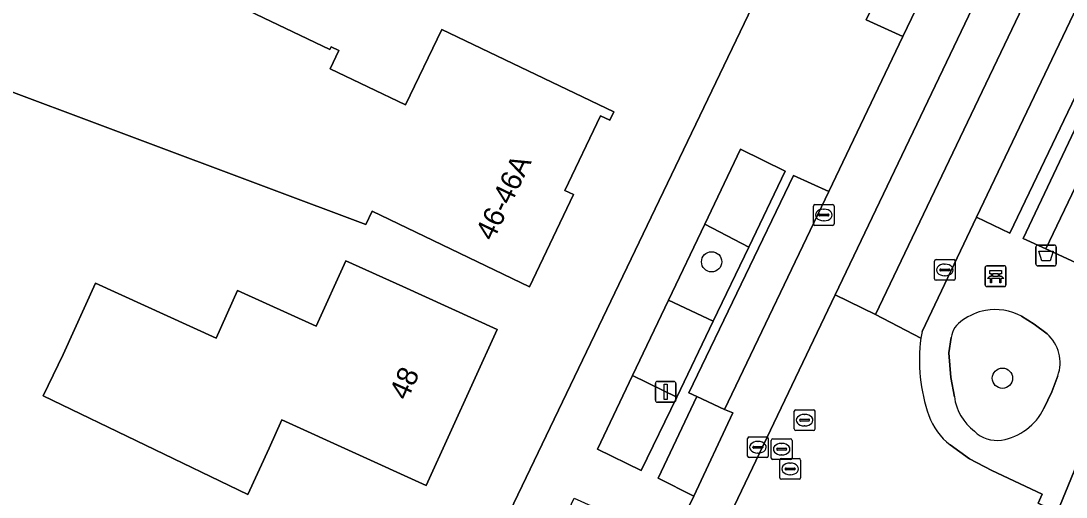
# Model space of a CAD drawing. Extents: x 161354 to 162026, y 386504 to 387460.
# Drawn here: x 161625.4 to 161675.8, y 386969.8 to 386992.8 of the extents above; entities that cross this region are included whole.
import ezdxf

# ---------------------------------------------------------------- set-up
doc = ezdxf.new("R2010")
doc.units = 0
for name, color, linetype in [('IMGEO_Afvalbak', 7, 'Continuous'), ('IMGEO_Bank', 7, 'Continuous'), ('IMGEO_Boom', 7, 'Continuous'), ('IMGEO_Erf', 7, 'Continuous'), ('IMGEO_Groenvoorziening', 7, 'Continuous'), ('IMGEO_Kolk', 7, 'Continuous'), ('IMGEO_Lichtmast', 7, 'Continuous'), ('IMGEO_Pand', 7, 'Continuous'), ('IMGEO_Pand_nummerreeks', 7, 'Continuous'), ('IMGEO_Parkeervlak_open', 7, 'Continuous'), ('IMGEO_Rijbaan_lokaal_open', 7, 'Continuous'), ('IMGEO_Rioolput', 7, 'Continuous'), ('IMGEO_Voetpad_open', 7, 'Continuous')]:
    doc.layers.add(name, color=color, linetype=linetype)

msp = doc.modelspace()

# ---------------------------------------------------------------- linework, layer by layer
at = {"layer": 'IMGEO_Afvalbak'}
for p, q in [((161674.479, 386981.982), (161675.269, 386981.982)), ((161675.269, 386981.982), (161674.479, 386981.982)), ((161674.379, 386981.082), (161674.379, 386981.882)), ((161674.379, 386981.882), (161674.379, 386981.082)), ((161675.369, 386981.882), (161675.369, 386981.082)), ((161675.369, 386981.082), (161675.369, 386981.882)), ((161675.269, 386980.982), (161674.479, 386980.982)), ((161674.479, 386980.982), (161675.269, 386980.982))]:
    msp.add_line(p, q, dxfattribs=at)
msp.add_lwpolyline([(161674.522, 386981.696), (161675.226, 386981.696), (161675.077, 386981.226), (161674.671, 386981.226), (161674.522, 386981.696)], dxfattribs=at)
for centre, start, end in [((161674.479, 386981.882), 90, 180), ((161674.479, 386981.882), 90, 180), ((161675.269, 386981.882), 0, 90), ((161675.269, 386981.882), 360, 90), ((161674.479, 386981.082), 180, 270), ((161674.479, 386981.082), 180, 270), ((161675.269, 386981.082), 270, 0), ((161675.269, 386981.082), 270, 0)]:
    msp.add_arc(centre, 0.1, start, end, dxfattribs=at)
at = {"layer": 'IMGEO_Bank'}
for p, q in [((161672.014, 386980.981), (161672.855, 386980.981)), ((161672.855, 386980.981), (161672.014, 386980.981)), ((161671.939, 386980.056), (161671.939, 386980.897)), ((161671.939, 386980.897), (161671.939, 386980.056)), ((161672.248, 386980.487), (161672.248, 386980.593)), ((161672.292, 386980.593), (161672.292, 386980.487)), ((161672.58, 386980.599), (161672.298, 386980.599)), ((161672.298, 386980.481), (161672.58, 386980.481)), ((161672.586, 386980.487), (161672.586, 386980.593)), ((161672.63, 386980.593), (161672.63, 386980.487)), ((161672.939, 386980.906), (161672.939, 386980.065)), ((161672.939, 386980.065), (161672.939, 386980.906)), ((161672.864, 386979.981), (161672.023, 386979.981)), ((161672.023, 386979.981), (161672.864, 386979.981)), ((161672.636, 386980.379), (161672.243, 386980.379))]:
    msp.add_line(p, q, dxfattribs=at)
for points in [[(161672.186, 386980.379), (161672.044, 386980.379), (161672.156, 386980.481), (161672.242, 386980.481)], [(161672.242, 386980.599), (161672.156, 386980.599), (161672.156, 386980.76), (161672.719, 386980.76), (161672.719, 386980.599), (161672.636, 386980.599)], [(161672.636, 386980.481), (161672.719, 386980.481), (161672.831, 386980.379), (161672.692, 386980.379)], [(161672.236, 386980.372), (161672.236, 386980.165), (161672.193, 386980.165), (161672.193, 386980.372)], [(161672.686, 386980.372), (161672.686, 386980.165), (161672.642, 386980.165), (161672.642, 386980.372)]]:
    msp.add_lwpolyline(points, dxfattribs=at)
for centre, radius, start, end in [((161672.017, 386980.903), 0.0779, 92.4484, 184.2845), ((161672.017, 386980.903), 0.0779, 92.4484, 184.2845), ((161672.861, 386980.903), 0.0779, 2.4484, 94.2845), ((161672.861, 386980.903), 0.0779, 2.4484, 94.2845), ((161672.241, 386980.592), 0.00671, 2.8957, 87.1043), ((161672.241, 386980.488), 0.00671, 272.8957, 357.1043), ((161672.298, 386980.592), 0.00671, 92.8957, 177.1043), ((161672.298, 386980.488), 0.00671, 182.8957, 267.1043), ((161672.58, 386980.592), 0.00671, 2.8957, 87.1043), ((161672.58, 386980.488), 0.00671, 272.8957, 357.1043), ((161672.637, 386980.592), 0.00671, 92.8957, 177.1043), ((161672.637, 386980.488), 0.00671, 182.8957, 267.1043), ((161672.017, 386980.059), 0.0779, 182.4484, 274.2845), ((161672.017, 386980.059), 0.0779, 182.4484, 274.2845), ((161672.186, 386980.372), 0.00671, 2.8957, 87.1043), ((161672.243, 386980.372), 0.00671, 92.8957, 177.1043), ((161672.635, 386980.372), 0.00671, 2.8957, 87.1043), ((161672.692, 386980.372), 0.00671, 92.8957, 177.1043), ((161672.861, 386980.059), 0.0779, 272.4484, 4.2845), ((161672.861, 386980.059), 0.0779, 272.4484, 4.2845)]:
    msp.add_arc(centre, radius, start, end, dxfattribs=at)
at = {"layer": 'IMGEO_Boom'}
for centre in [(161658.732, 386981.177), (161672.771, 386975.56)]:
    msp.add_circle(centre, 0.489, dxfattribs=at)
at = {"layer": 'IMGEO_Erf'}
for points in [[(161639.028, 387030.532), (161638.508, 387014.846), (161634.791, 387006.94), (161635.073, 387006.762), (161631.945, 387000), (161630.209, 386996.251), (161636.023, 386993.468), (161640.299, 386991.421), (161640.365, 386991.559), (161640.742, 386991.379), (161640.319, 386990.494), (161643.964, 386988.749), (161645.705, 386992.384), (161649.5, 386990.567), (161654.01, 386988.408), (161653.819, 386988.01), (161653.371, 386988.225), (161651.645, 386984.62), (161652.067, 386984.418), (161649.94, 386979.976), (161642.34, 386983.614)], [(161627.852, 386924.437), (161646.394, 386963.7), (161647.042, 386965.072), (161663.81, 387000), (161675.489, 387024.329)], [(161642.34, 386983.614), (161642.038, 386982.983), (161637.356, 386984.735), (161616.468, 386992.553)]]:
    msp.add_lwpolyline(points, dxfattribs=at)
msp.add_lwpolyline([(161641.076, 386981.232), (161643.83, 386979.98), (161648.381, 386977.91), (161644.961, 386970.388), (161637.992, 386973.556), (161637.37, 386972.188), (161636.348, 386969.941), (161626.462, 386974.71), (161627.426, 386976.709), (161628.998, 386980.143), (161634.812, 386977.499), (161635.853, 386979.789), (161639.638, 386978.068)], close=True, dxfattribs=at)
at = {"layer": 'IMGEO_Groenvoorziening'}
for points in [[(161678.258, 386988.893), (161677.127, 386989.4), (161673.763, 386982.308), (161674.862, 386981.801)], [(161680.347, 386987.958), (161678.258, 386988.893), (161674.862, 386981.801), (161677.136, 386980.752)], [(161662.286, 386985.549), (161660.12, 386986.613), (161658.399, 386983), (161660.524, 386981.884)], [(161660.524, 386981.884), (161658.399, 386983), (161656.647, 386979.321), (161658.807, 386978.313)], [(161658.807, 386978.313), (161656.647, 386979.321), (161654.917, 386975.688), (161657.046, 386974.651)], [(161657.046, 386974.651), (161654.917, 386975.688), (161653.224, 386972.132), (161655.338, 386971.098)], [(161659.764, 386973.893), (161659.348, 386974.057), (161658.012, 386974.684), (161656.15, 386970.736), (161657.878, 386969.873)]]:
    msp.add_lwpolyline(points, close=True, dxfattribs=at)
for points in [[(161674.923, 386977.7), (161674.308, 386978.168), (161673.689, 386978.556)], [(161670.293, 386977.521), (161670.182, 386976.789), (161670.271, 386975.601), (161670.449, 386974.669)], [(161674.768, 386974.097), (161675.156, 386974.901), (161675.437, 386975.672)]]:
    msp.add_lwpolyline(points, dxfattribs=at)
for centre, radius, start, end in [((161672.464, 386976.096), 2.781, 100.7237, 125.4842), ((161672.433, 386976.235), 2.639, 61.5738, 100.6227), ((161671.487, 386977.335), 1.208, 121.86, 171.1385), ((161673.73, 386976.319), 1.825, 339.2507, 49.1937), ((161672.938, 386974.996), 2.51, 187.4792, 232.6228), ((161672.257, 386975.336), 2.8, 279.7591, 333.7281), ((161672.492, 386974.092), 1.534, 225.3394, 278.9946)]:
    msp.add_arc(centre, radius, start, end, dxfattribs=at)
at = {"layer": 'IMGEO_Kolk'}
for p, q in [((161663.647, 386983.011), (161663.647, 386983.863)), ((161663.722, 386983.937), (161664.574, 386983.937)), ((161664.135, 386983.717), (161664.16, 386983.717)), ((161664.648, 386983.863), (161664.648, 386983.011)), ((161663.906, 386983.431), (161663.906, 386983.443)), ((161664.344, 386983.394), (161663.946, 386983.394)), ((161663.949, 386983.48), (161664.347, 386983.48)), ((161664.158, 386983.157), (161664.133, 386983.157)), ((161664.39, 386983.443), (161664.39, 386983.431)), ((161664.574, 386982.937), (161663.722, 386982.937)), ((161669.49, 386980.359), (161669.49, 386981.211)), ((161669.565, 386981.285), (161670.417, 386981.285)), ((161669.978, 386981.065), (161670.003, 386981.065)), ((161670.491, 386981.211), (161670.491, 386980.359)), ((161669.749, 386980.779), (161669.749, 386980.791)), ((161670.187, 386980.742), (161669.789, 386980.742)), ((161669.792, 386980.828), (161670.19, 386980.828)), ((161670.001, 386980.505), (161669.976, 386980.505)), ((161670.233, 386980.791), (161670.233, 386980.779)), ((161670.417, 386980.285), (161669.565, 386980.285))]:
    msp.add_line(p, q, dxfattribs=at)
for points in [[(161663.647, 386983.011), (161663.647, 386983.863)], [(161663.722, 386983.937), (161664.574, 386983.937)], [(161664.648, 386983.863), (161664.648, 386983.011)], [(161664.574, 386982.937), (161663.722, 386982.937)], [(161669.49, 386980.359), (161669.49, 386981.211)], [(161669.565, 386981.285), (161670.417, 386981.285)], [(161670.491, 386981.211), (161670.491, 386980.359)], [(161670.417, 386980.285), (161669.565, 386980.285)]]:
    msp.add_lwpolyline(points, dxfattribs=at)
for centre, radius, start, end in [((161663.724, 386983.861), 0.0765, 91.552, 178.448), ((161663.724, 386983.861), 0.0765, 91.552, 178.448), ((161664.572, 386983.861), 0.0765, 1.552, 88.448), ((161664.572, 386983.861), 0.0765, 1.552, 88.448), ((161663.724, 386983.013), 0.0765, 181.552, 268.448), ((161663.724, 386983.013), 0.0765, 181.552, 268.448), ((161663.946, 386983.44), 0.0403, 85.8775, 175.7526), ((161663.943, 386983.43), 0.0366, 178.938, 274.7102), ((161664.347, 386983.437), 0.043, 264.8664, 352.4533), ((161664.351, 386983.442), 0.0386, 1.7309, 96.639), ((161664.572, 386983.013), 0.0765, 271.552, 358.448), ((161664.572, 386983.013), 0.0765, 271.552, 358.448), ((161669.567, 386981.209), 0.0765, 91.552, 178.448), ((161669.567, 386981.209), 0.0765, 91.552, 178.448), ((161670.415, 386981.209), 0.0765, 1.552, 88.448), ((161670.415, 386981.209), 0.0765, 1.552, 88.448), ((161669.789, 386980.788), 0.0403, 85.8775, 175.7526), ((161669.786, 386980.778), 0.0366, 178.938, 274.7102), ((161670.19, 386980.785), 0.043, 264.8664, 352.4533), ((161670.194, 386980.79), 0.0386, 1.7309, 96.639), ((161669.567, 386980.361), 0.0765, 181.552, 268.448), ((161669.567, 386980.361), 0.0765, 181.552, 268.448), ((161670.415, 386980.361), 0.0765, 271.552, 358.448), ((161670.415, 386980.361), 0.0765, 271.552, 358.448)]:
    msp.add_arc(centre, radius, start, end, dxfattribs=at)
for centre, major_axis, ratio, start_param, end_param in [((161664.134, 386983.437), (-0.387, 0.002), 0.722429, 4.712389, 7.853982), ((161664.159, 386983.437), (-0.39, 0.002), 0.717154, 1.570796, 4.712389), ((161669.977, 386980.785), (-0.387, 0.002), 0.722429, 4.712389, 7.853982), ((161670.002, 386980.785), (-0.39, 0.002), 0.717154, 1.570796, 4.712389)]:
    msp.add_ellipse(centre, major_axis=major_axis, ratio=ratio, start_param=start_param, end_param=end_param, dxfattribs=at)
at = {"layer": 'IMGEO_Lichtmast'}
for p, q in [((161656.018, 386974.501), (161656.018, 386975.301)), ((161656.018, 386975.301), (161656.018, 386974.501)), ((161656.118, 386975.401), (161656.908, 386975.401)), ((161656.908, 386975.401), (161656.118, 386975.401)), ((161657.008, 386975.301), (161657.008, 386974.501)), ((161657.008, 386974.501), (161657.008, 386975.301)), ((161656.908, 386974.401), (161656.118, 386974.401)), ((161656.118, 386974.401), (161656.908, 386974.401))]:
    msp.add_line(p, q, dxfattribs=at)
msp.add_lwpolyline([(161656.438, 386975.276), (161656.588, 386975.276), (161656.588, 386974.526), (161656.438, 386974.526), (161656.438, 386975.276)], dxfattribs=at)
for centre, start, end in [((161656.118, 386975.301), 90, 180), ((161656.118, 386975.301), 90, 180), ((161656.908, 386975.301), 0, 90), ((161656.908, 386975.301), 360, 90), ((161656.118, 386974.501), 180, 270), ((161656.118, 386974.501), 180, 270), ((161656.908, 386974.501), 270, 0), ((161656.908, 386974.501), 270, 0)]:
    msp.add_arc(centre, 0.1, start, end, dxfattribs=at)
at = {"layer": 'IMGEO_Pand'}
msp.add_lwpolyline([(161616.468, 386992.553), (161637.356, 386984.735), (161642.038, 386982.983), (161642.34, 386983.614), (161649.94, 386979.976), (161652.067, 386984.418), (161651.645, 386984.62), (161653.371, 386988.225), (161653.819, 386988.01), (161654.01, 386988.408), (161649.5, 386990.567), (161645.705, 386992.384), (161643.964, 386988.749), (161640.319, 386990.494), (161640.742, 386991.379), (161640.365, 386991.559), (161640.299, 386991.421), (161636.023, 386993.468), (161630.209, 386996.251), (161631.945, 387000), (161635.073, 387006.762), (161634.791, 387006.94), (161638.508, 387014.846), (161639.028, 387030.532)], dxfattribs=at)
msp.add_lwpolyline([(161648.381, 386977.91), (161643.83, 386979.98), (161641.076, 386981.232), (161639.638, 386978.068), (161635.853, 386979.789), (161634.812, 386977.499), (161628.998, 386980.143), (161627.426, 386976.709), (161626.462, 386974.71), (161636.348, 386969.941), (161637.37, 386972.188), (161637.992, 386973.556), (161644.961, 386970.388)], close=True, dxfattribs=at)
at = {"layer": 'IMGEO_Parkeervlak_open'}
for points in [[(161686.779, 387015.299), (161671.511, 386983.329), (161673.133, 386982.564), (161688.427, 387014.484)], [(161672.284, 387001.058), (161670.591, 387001.885), (161666.2, 386992.848), (161667.967, 386992.057)], [(161664.397, 386984.566), (161662.691, 386985.348), (161657.639, 386974.851), (161658.012, 386974.684), (161659.348, 386974.057)]]:
    msp.add_lwpolyline(points, close=True, dxfattribs=at)
at = {"layer": 'IMGEO_Rijbaan_lokaal_open'}
for points in [[(161682.437, 387021.149), (161681.983, 387021.329), (161681.574, 387020.458), (161683.75, 387019.375), (161683.561, 387018.983), (161680.977, 387013.629), (161664.695, 386979.587), (161666.643, 386978.635), (161685.481, 387018.029), (161686.934, 387021.178)], [(161686.934, 387021.178), (161685.481, 387018.029), (161666.643, 386978.635), (161668.836, 386977.492)], [(161668.89, 386977.819), (161671.511, 386983.329), (161686.779, 387015.299)], [(161668.836, 386977.492), (161666.643, 386978.635), (161664.695, 386979.587), (161658.609, 386966.862), (161656.852, 386967.721), (161656.79, 386967.618), (161655.829, 386965.562), (161657.516, 386964.711), (161659.528, 386963.762), (161661.265, 386962.944), (161661.712, 386963.875)], [(161668.856, 386966.469), (161673.318, 386964.474), (161675.409, 386969.085), (161675.367, 386969.105), (161674.495, 386969.525), (161674.68, 386969.96), (161672.256, 386971.1), (161671.176, 386971.663), (161670.245, 386972.344)]]:
    msp.add_lwpolyline(points, dxfattribs=at)
msp.add_lwpolyline([(161680.977, 387013.629), (161683.561, 387018.983), (161683.75, 387019.375), (161681.574, 387020.458), (161677.895, 387012.773), (161675.699, 387008.193), (161672.284, 387001.058), (161667.967, 386992.057), (161664.397, 386984.566), (161659.348, 386974.057), (161659.764, 386973.893), (161657.878, 386969.873), (161656.852, 386967.721), (161658.609, 386966.862), (161664.695, 386979.587)], close=True, dxfattribs=at)
for centre, radius, start, end in [((161676.526, 386976.402), 7.767, 171.9348, 199.8576), ((161675.455, 386976.567), 6.683, 169.2022, 172.0437), ((161672.126, 386974.78), 3.078, 199.2723, 232.3205)]:
    msp.add_arc(centre, radius, start, end, dxfattribs=at)
at = {"layer": 'IMGEO_Rioolput'}
for p, q in [((161662.721, 386973.11), (161662.721, 386973.962)), ((161662.796, 386974.036), (161663.648, 386974.036)), ((161663.722, 386973.962), (161663.722, 386973.11)), ((161662.98, 386973.53), (161662.98, 386973.542)), ((161663.418, 386973.493), (161663.02, 386973.493)), ((161663.023, 386973.579), (161663.421, 386973.579)), ((161663.209, 386973.816), (161663.234, 386973.816)), ((161663.464, 386973.542), (161663.464, 386973.53)), ((161663.648, 386973.036), (161662.796, 386973.036)), ((161663.232, 386973.256), (161663.207, 386973.256)), ((161660.468, 386971.802), (161660.468, 386972.654)), ((161660.543, 386972.728), (161661.395, 386972.728)), ((161660.956, 386972.508), (161660.981, 386972.508)), ((161661.469, 386972.654), (161661.469, 386971.802)), ((161661.613, 386971.709), (161661.613, 386972.561)), ((161661.688, 386972.635), (161662.54, 386972.635)), ((161662.101, 386972.415), (161662.126, 386972.415)), ((161662.614, 386972.561), (161662.614, 386971.709)), ((161660.727, 386972.222), (161660.727, 386972.234)), ((161661.165, 386972.185), (161660.767, 386972.185)), ((161660.77, 386972.271), (161661.168, 386972.271)), ((161660.979, 386971.948), (161660.954, 386971.948)), ((161661.211, 386972.234), (161661.211, 386972.222)), ((161661.872, 386972.129), (161661.872, 386972.141)), ((161662.31, 386972.092), (161661.912, 386972.092)), ((161661.915, 386972.178), (161662.313, 386972.178)), ((161662.356, 386972.141), (161662.356, 386972.129)), ((161661.395, 386971.728), (161660.543, 386971.728)), ((161662.54, 386971.635), (161661.688, 386971.635)), ((161662.024, 386970.757), (161662.024, 386971.609)), ((161662.124, 386971.855), (161662.099, 386971.855)), ((161662.099, 386971.683), (161662.951, 386971.683)), ((161662.512, 386971.463), (161662.537, 386971.463)), ((161663.025, 386971.609), (161663.025, 386970.757)), ((161662.283, 386971.177), (161662.283, 386971.189)), ((161662.721, 386971.14), (161662.323, 386971.14)), ((161662.326, 386971.226), (161662.724, 386971.226)), ((161662.535, 386970.903), (161662.51, 386970.903)), ((161662.767, 386971.189), (161662.767, 386971.177)), ((161662.951, 386970.683), (161662.099, 386970.683))]:
    msp.add_line(p, q, dxfattribs=at)
for points in [[(161662.721, 386973.11), (161662.721, 386973.962)], [(161662.796, 386974.036), (161663.648, 386974.036)], [(161663.722, 386973.962), (161663.722, 386973.11)], [(161663.648, 386973.036), (161662.796, 386973.036)], [(161660.468, 386971.802), (161660.468, 386972.654)], [(161660.543, 386972.728), (161661.395, 386972.728)], [(161661.469, 386972.654), (161661.469, 386971.802)], [(161661.613, 386971.709), (161661.613, 386972.561)], [(161661.688, 386972.635), (161662.54, 386972.635)], [(161662.614, 386972.561), (161662.614, 386971.709)], [(161661.395, 386971.728), (161660.543, 386971.728)], [(161662.54, 386971.635), (161661.688, 386971.635)], [(161662.024, 386970.757), (161662.024, 386971.609)], [(161662.099, 386971.683), (161662.951, 386971.683)], [(161663.025, 386971.609), (161663.025, 386970.757)], [(161662.951, 386970.683), (161662.099, 386970.683)]]:
    msp.add_lwpolyline(points, dxfattribs=at)
for centre, radius, start, end in [((161662.798, 386973.96), 0.0765, 91.552, 178.448), ((161662.798, 386973.96), 0.0765, 91.552, 178.448), ((161663.646, 386973.96), 0.0765, 1.552, 88.448), ((161663.646, 386973.96), 0.0765, 1.552, 88.448), ((161663.02, 386973.539), 0.0403, 85.8775, 175.7526), ((161663.017, 386973.529), 0.0366, 178.938, 274.7102), ((161663.421, 386973.536), 0.043, 264.8664, 352.4533), ((161663.425, 386973.541), 0.0386, 1.7309, 96.639), ((161662.798, 386973.112), 0.0765, 181.552, 268.448), ((161662.798, 386973.112), 0.0765, 181.552, 268.448), ((161663.646, 386973.112), 0.0765, 271.552, 358.448), ((161663.646, 386973.112), 0.0765, 271.552, 358.448), ((161660.545, 386972.652), 0.0765, 91.552, 178.448), ((161660.545, 386972.652), 0.0765, 91.552, 178.448), ((161661.393, 386972.652), 0.0765, 1.552, 88.448), ((161661.393, 386972.652), 0.0765, 1.552, 88.448), ((161661.69, 386972.559), 0.0765, 91.552, 178.448), ((161661.69, 386972.559), 0.0765, 91.552, 178.448), ((161662.538, 386972.559), 0.0765, 1.552, 88.448), ((161662.538, 386972.559), 0.0765, 1.552, 88.448), ((161660.767, 386972.231), 0.0403, 85.8775, 175.7526), ((161660.764, 386972.221), 0.0366, 178.938, 274.7102), ((161661.168, 386972.228), 0.043, 264.8664, 352.4533), ((161661.172, 386972.233), 0.0386, 1.7309, 96.639), ((161661.912, 386972.138), 0.0403, 85.8775, 175.7526), ((161661.909, 386972.128), 0.0366, 178.938, 274.7102), ((161662.313, 386972.135), 0.043, 264.8664, 352.4533), ((161662.317, 386972.14), 0.0386, 1.7309, 96.639), ((161660.545, 386971.804), 0.0765, 181.552, 268.448), ((161660.545, 386971.804), 0.0765, 181.552, 268.448), ((161661.393, 386971.804), 0.0765, 271.552, 358.448), ((161661.393, 386971.804), 0.0765, 271.552, 358.448), ((161661.69, 386971.711), 0.0765, 181.552, 268.448), ((161661.69, 386971.711), 0.0765, 181.552, 268.448), ((161662.101, 386971.607), 0.0765, 91.552, 178.448), ((161662.101, 386971.607), 0.0765, 91.552, 178.448), ((161662.538, 386971.711), 0.0765, 271.552, 358.448), ((161662.538, 386971.711), 0.0765, 271.552, 358.448), ((161662.949, 386971.607), 0.0765, 1.552, 88.448), ((161662.949, 386971.607), 0.0765, 1.552, 88.448), ((161662.323, 386971.186), 0.0403, 85.8775, 175.7526), ((161662.32, 386971.176), 0.0366, 178.938, 274.7102), ((161662.724, 386971.183), 0.043, 264.8664, 352.4533), ((161662.728, 386971.188), 0.0386, 1.7309, 96.639), ((161662.101, 386970.759), 0.0765, 181.552, 268.448), ((161662.101, 386970.759), 0.0765, 181.552, 268.448), ((161662.949, 386970.759), 0.0765, 271.552, 358.448), ((161662.949, 386970.759), 0.0765, 271.552, 358.448)]:
    msp.add_arc(centre, radius, start, end, dxfattribs=at)
for centre, major_axis, ratio, start_param, end_param in [((161663.208, 386973.536), (-0.387, 0.002), 0.722429, 4.712389, 7.853982), ((161663.233, 386973.536), (-0.39, 0.002), 0.717154, 1.570796, 4.712389), ((161660.955, 386972.228), (-0.387, 0.002), 0.722429, 4.712389, 7.853982), ((161660.98, 386972.228), (-0.39, 0.002), 0.717154, 1.570796, 4.712389), ((161662.1, 386972.135), (-0.387, 0.002), 0.722429, 4.712389, 7.853982), ((161662.125, 386972.135), (-0.39, 0.002), 0.717154, 1.570796, 4.712389), ((161662.511, 386971.183), (-0.387, 0.002), 0.722429, 4.712389, 7.853982), ((161662.536, 386971.183), (-0.39, 0.002), 0.717154, 1.570796, 4.712389)]:
    msp.add_ellipse(centre, major_axis=major_axis, ratio=ratio, start_param=start_param, end_param=end_param, dxfattribs=at)
at = {"layer": 'IMGEO_Voetpad_open'}
for points in [[(161670.245, 386972.344), (161671.176, 386971.663), (161672.256, 386971.1), (161674.68, 386969.96), (161674.495, 386969.525), (161675.367, 386969.105), (161675.409, 386969.085), (161677.419, 386973.992), (161689.028, 387000), (161692.864, 387007.756), (161695.643, 387012.888), (161703.036, 387025.535), (161713.413, 387041.445)], [(161675.489, 387024.329), (161663.81, 387000), (161647.042, 386965.072), (161646.394, 386963.7), (161648.603, 386962.721), (161650.919, 386961.618), (161651.637, 386961.362), (161653.801, 386965.856)], [(161657.878, 386969.873), (161656.15, 386970.736), (161658.012, 386974.684), (161657.639, 386974.851), (161662.691, 386985.348), (161664.397, 386984.566), (161667.967, 386992.057), (161666.2, 386992.848), (161670.591, 387001.885), (161672.284, 387001.058), (161675.699, 387008.193), (161673.999, 387009.024), (161676.226, 387013.601), (161677.895, 387012.773), (161681.574, 387020.458), (161681.983, 387021.329), (161682.437, 387021.149)], [(161688.332, 387018.449), (161687.597, 387016.959), (161686.779, 387015.299), (161688.427, 387014.484), (161673.133, 386982.564), (161671.511, 386983.329), (161668.89, 386977.819)], [(161673.689, 386978.556), (161674.308, 386978.168), (161674.923, 386977.7)], [(161670.449, 386974.669), (161670.271, 386975.601), (161670.182, 386976.789), (161670.293, 386977.521)], [(161675.437, 386975.672), (161675.156, 386974.901), (161674.768, 386974.097)], [(161677.419, 386973.992), (161675.409, 386969.085), (161676.467, 386968.571), (161683.099, 386965.38), (161699.061, 386957.966), (161699.268, 386958.42), (161702.613, 386956.861), (161702.406, 386956.407)], [(161653.954, 386965.983), (161653.914, 386966.103), (161651.04, 386967.525), (161652.091, 386969.772), (161654.877, 386968.52), (161656.79, 386967.618), (161656.852, 386967.721), (161657.878, 386969.873)]]:
    msp.add_lwpolyline(points, dxfattribs=at)
for points in [[(161680.347, 386987.958), (161677.136, 386980.752), (161674.862, 386981.801), (161673.763, 386982.308), (161677.127, 386989.4), (161678.258, 386988.893)], [(161658.807, 386978.313), (161657.046, 386974.651), (161655.338, 386971.098), (161653.224, 386972.132), (161654.917, 386975.688), (161656.647, 386979.321), (161658.399, 386983), (161660.12, 386986.613), (161662.286, 386985.549), (161660.524, 386981.884)]]:
    msp.add_lwpolyline(points, close=True, dxfattribs=at)
for centre, radius, start, end in [((161672.464, 386976.096), 2.781, 100.7237, 125.4842), ((161672.433, 386976.235), 2.639, 61.5738, 100.6227), ((161671.487, 386977.335), 1.208, 121.86, 171.1385), ((161676.526, 386976.402), 7.767, 171.9348, 199.8576), ((161675.455, 386976.567), 6.683, 169.2022, 172.0437), ((161673.73, 386976.319), 1.825, 339.2507, 49.1937), ((161672.938, 386974.996), 2.51, 187.4792, 232.6228), ((161672.257, 386975.336), 2.8, 279.7591, 333.7281), ((161672.126, 386974.78), 3.078, 199.2723, 232.3205), ((161672.492, 386974.092), 1.534, 225.3394, 278.9946)]:
    msp.add_arc(centre, radius, start, end, dxfattribs=at)

# ---------------------------------------------------------------- texts
at = {"layer": 'IMGEO_Pand_nummerreeks'}
for s, rotation, p in [('46-46A', 64.2277, (161648.185, 386982.136)), ('48', 65.5521, (161644.036, 386974.442))]:
    msp.add_text(s, height=1, rotation=rotation, dxfattribs=at).set_placement(p)

doc.saveas('drawing.dxf')
